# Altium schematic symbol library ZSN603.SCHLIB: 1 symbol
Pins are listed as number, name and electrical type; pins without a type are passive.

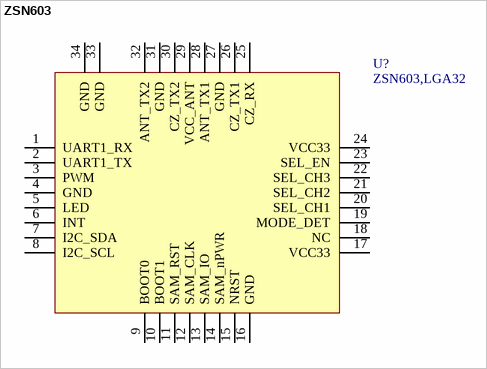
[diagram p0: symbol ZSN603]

## ZSN603
designator U?, comment ZSN603,LGA32
ZSN600,LGA32,ZLG; 封装: LGA-32; 器件优选方案: 待导入物料
pins: 1 UART1_RX, 2 UART1_TX, 3 PWM, 4 GND, 5 LED, 6 INT, 7 I2C_SDA, 8 I2C_SCL, 9 BOOT0, 10 BOOT1, 11 SAM_RST, 12 SAM_CLK, 13 SAM_IO, 14 SAM_nPWR, 15 NRST, 16 GND, 17 VCC33, 18 NC, 19 MODE_DET, 20 SEL_CH1, 21 SEL_CH2, 22 SEL_CH3, 23 SEL_EN, 24 VCC33, 25 CZ_RX, 26 CZ_TX1, 27 GND, 28 ANT_TX1, 29 VCC_ANT, 30 CZ_TX2, 31 GND, 32 ANT_TX2, 33 GND, 34 GND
